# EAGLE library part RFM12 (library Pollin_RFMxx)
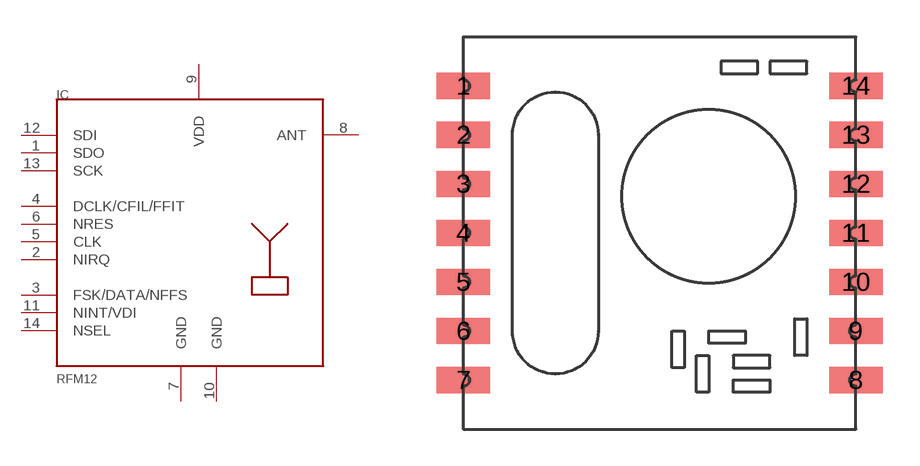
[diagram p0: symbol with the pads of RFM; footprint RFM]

Designator prefix IC

## RFM12  [RFM]
1  SDO
2  NIRQ
3  FSK/DATA/NFFS
4  DCLK/CFIL/FFIT
5  CLK
6  NRES
7  GND  pwr
8  ANT  out
9  VDD  pwr
10  GND  pwr
11  NINT/VDI
12  SDI
13  SCK
14  NSEL

## Footprint RFM (pad centres in mm)
smd 2.184 x 1.067: 1 0,14; 2 0,12; 3 0,10; 4 0,8; 5 0,6; 6 0,4; 7 0,2; 8 16,2; 9 16,4; 10 16,6; 11 16,8; 12 16,10; 13 16,12; 14 16,14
